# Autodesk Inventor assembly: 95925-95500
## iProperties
Author: Administrator
Created: 2002-04
Part Number: 95925-95500
Document SubType Name: Assembly
Designer: Administrator
Control State: 0
Master: False
Checked Out: False
PropertySet Name: Design Tracking Control
Shininess: 64.0
Angle Display Precision: 2
Document Length Units: 11272
Document Angle Units: 11286
Document Time Units: 11279
Document Mass Units: 11290
Document Length Units Precision: 3
Document Angle Units Precision: 2
Compacted: True
PropertySet Name: _Private Model Information
Density: 0.0
Volumn: 0.0
Area: 0.0
PropertySet Name: Model Information
